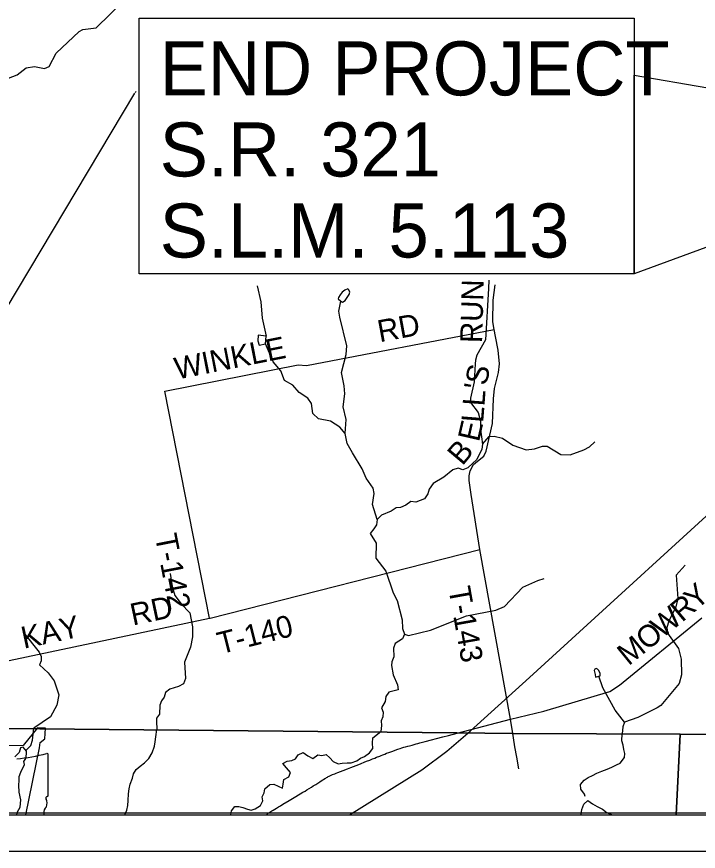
# Model space of a CAD drawing. Extents: x 0 to 34, y 0 to 22.
# Drawn here: x 5.601 to 7.367, y 14 to 16.162 of the extents above; entities that cross this region are included whole.
import ezdxf

# ---------------------------------------------------------------- set-up
doc = ezdxf.new("R2010")
doc.units = 0
for name, color, linetype in [('Default', 7, 'Continuous'), ('GM_X_County_Road', 7, 'Continuous'), ('GM_X_County_Road_Text', 7, 'Continuous'), ('GM_X_Major_River', 7, 'Continuous'), ('GM_X_Minor_Lake', 7, 'Continuous'), ('GM_X_Minor_River', 7, 'Continuous'), ('GM_X_Rail_Line', 7, 'Continuous'), ('GM_X_Township_Road', 7, 'Continuous'), ('GM_X_Township_Road_Text', 7, 'Continuous'), ('SH_Cut_Line', 7, 'Continuous'), ('SH_Data', 7, 'Continuous')]:
    doc.layers.add(name, color=color, linetype=linetype)

msp = doc.modelspace()

# ---------------------------------------------------------------- linework, layer by layer
at = {"layer": 'Default'}
msp.add_line((5.9098, 15.9686), (5.9078, 15.9652), dxfattribs=at)
for points in [[(2.3212, 18.6531), (2.2797, 17.8302), (2.2668, 17.0936), (2.2632, 16.8811), (2.258, 16.7775), (2.1837, 15.746), (2.1, 14.637), (2.1, 14.4457), (2.4012, 14.4298), (2.4436, 14.4284), (2.5802, 14.4232), (3.783, 14.3901), (4.0144, 14.3862), (4.819, 14.3535), (4.9366, 14.3421), (5.2368, 14.8438), (5.4205, 15.1508), (5.9071, 15.964)], [(4.8842, 14.0941), (5.6247, 14.0941), (5.6602, 14.2685), (5.6616, 14.2819), (5.6736, 14.2915), (5.6759, 14.3194), (5.6545, 14.3197), (5.6182, 14.274), (5.4889, 14.273)], [(5.6828, 14.1454), (5.6828, 14.1454), (5.6828, 14.1454), (5.6828, 14.2503)], [(5.3532, 14.2417), (5.3532, 14.0941), (5.6721, 14.0941)]]:
    msp.add_lwpolyline(points, dxfattribs=at)
for points in [[(7.2008, 15.4965), (5.9187, 15.4965), (5.9187, 16.1585), (7.2008, 16.1585)], [(7.2008, 16.011), (8.1557, 15.8464), (7.2008, 15.4965)], [(2.1, 14.4457), (2.1, 14.243), (2.102, 14.2411), (2.1319, 14.2168), (2.1359, 14.2103), (2.1425, 14.1753), (2.1455, 14.1482), (2.1436, 14.1288), (2.1399, 14.114), (2.1382, 14.1043), (2.1342, 14.0941), (7.3096, 14.0941), (7.3204, 14.3032), (6.8864, 14.3056), (6.7418, 14.3069), (5.4793, 14.3187), (5.0616, 14.3309), (4.9366, 14.3421), (4.819, 14.3535), (4.0144, 14.3862), (3.783, 14.3901), (2.5802, 14.4232), (2.4436, 14.4284), (2.4012, 14.4298)], [(7.3096, 14.0941), (8.9, 14.0941), (8.9, 14.2922), (8.7041, 14.2905), (8.6074, 14.2911), (7.3204, 14.3032)]]:
    msp.add_lwpolyline(points, close=True, dxfattribs=at)
for centre, major_axis, start_param, end_param in [((5.5654, 14.518), (0.3495, 0), 4.814394, 5.042369), ((5.6792, 14.2505), (0.00367, 0), 6.197627, 7.989034), ((5.682, 14.1377), (0.00568, 0), 1.883976, 3.671073), ((5.6789, 14.145), (0.00393, 0), 5.054544, 6.418171), ((5.6458, 14.1245), (0.0341, 0), 5.934695, 6.695948), ((5.696, 14.1016), (0.0248, 0), 2.387724, 3.262537), ((5.585, 14.0883), (0.0874, 0), 0.083727, 0.156833)]:
    msp.add_ellipse(centre, major_axis=major_axis, ratio=0.8, start_param=start_param, end_param=end_param, dxfattribs=at)
at = {"layer": 'GM_X_County_Road'}
for points in [[(6.7421, 14.3064), (6.8805, 14.3426), (6.9665, 14.3634), (7.1378, 14.4138), (7.1628, 14.4308), (7.3766, 14.605)], [(6.2486, 14.0941), (6.2487, 14.0942), (6.2501, 14.0959), (6.2513, 14.0971), (6.2528, 14.0984), (6.2544, 14.0996), (6.2569, 14.1014), (6.2598, 14.1033), (6.2625, 14.105), (6.2658, 14.107), (6.2696, 14.1092), (6.2738, 14.1116), (6.2792, 14.1148), (6.2848, 14.1182), (6.2909, 14.1219), (6.3066, 14.1313), (6.3242, 14.1418), (6.3426, 14.1528), (6.3481, 14.1561), (6.3531, 14.1591), (6.359, 14.1627), (6.3645, 14.1662), (6.3694, 14.1694), (6.3758, 14.1735), (6.3861, 14.1801), (6.3922, 14.1839), (6.3963, 14.1864), (6.3994, 14.1883), (6.402, 14.1899), (6.404, 14.1912), (6.4061, 14.1924), (6.4082, 14.1935), (6.4105, 14.1946), (6.414, 14.1962), (6.4196, 14.1986), (6.425, 14.2008), (6.4291, 14.2024), (6.4331, 14.204), (6.4398, 14.2065), (6.4472, 14.2093), (6.4578, 14.2135), (6.4668, 14.217), (6.4876, 14.2253), (6.5078, 14.2333), (6.5158, 14.2364), (6.5233, 14.2393), (6.5289, 14.2416), (6.5336, 14.2435), (6.5417, 14.2468), (6.5456, 14.2484), (6.5495, 14.25), (6.5546, 14.252), (6.5596, 14.2539), (6.5652, 14.256), (6.5708, 14.2581), (6.5755, 14.2598), (6.5817, 14.262), (6.5883, 14.2643), (6.5943, 14.2662), (6.5989, 14.2677), (6.6042, 14.2694), (6.6087, 14.2707), (6.6141, 14.2722), (6.6191, 14.2736), (6.6255, 14.2754), (6.6311, 14.2768), (6.6359, 14.2781), (6.6405, 14.2794), (6.646, 14.2809), (6.6595, 14.2845), (6.7052, 14.2965), (6.7197, 14.3003), (6.7421, 14.3064)]]:
    msp.add_lwpolyline(points, dxfattribs=at)
at = {"layer": 'GM_X_Major_River'}
msp.add_lwpolyline([(7.0636, 14.0941), (7.064, 14.0967), (7.0657, 14.1085), (7.0708, 14.1217), (7.0805, 14.1314), (7.0929, 14.1229), (7.1053, 14.1159), (7.1188, 14.1088), (7.1308, 14.0999), (7.1448, 14.0944), (7.1452, 14.0941)], dxfattribs=at)
at = {"layer": 'GM_X_Minor_Lake'}
for points in [[(6.4411, 15.4251), (6.4448, 15.4227), (6.4525, 15.4272), (6.4575, 15.4351), (6.4625, 15.4422), (6.4645, 15.449), (6.4616, 15.4548), (6.459, 15.4571), (6.4513, 15.4538), (6.4444, 15.4486), (6.4394, 15.4418), (6.4348, 15.435)], [(6.4348, 15.435), (6.4337, 15.4316), (6.4411, 15.4251)], [(6.2461, 15.3145), (6.2475, 15.3342), (6.2266, 15.3368), (6.2257, 15.3228), (6.2289, 15.3117)], [(6.2289, 15.3117), (6.2461, 15.3145)], [(7.1092, 14.4538), (7.1126, 14.4549), (7.1127, 14.4606), (7.1098, 14.4682), (7.1056, 14.4717), (7.1022, 14.4737), (7.0988, 14.4718), (7.0972, 14.468), (7.0994, 14.4619), (7.1001, 14.4577), (7.1012, 14.4513)], [(7.1012, 14.4513), (7.1092, 14.4538)], [(5.601, 14.0941), (5.6033, 14.102), (5.6099, 14.1144), (5.612, 14.1333), (5.607, 14.1531), (5.6065, 14.1717), (5.6078, 14.1835), (5.6075, 14.1937), (5.6118, 14.2047), (5.6212, 14.2246), (5.6198, 14.2323), (5.6244, 14.2405), (5.6268, 14.2526), (5.6262, 14.2591), (5.6176, 14.2702), (5.6108, 14.2677), (5.6072, 14.256), (5.5961, 14.2451)]]:
    msp.add_lwpolyline(points, dxfattribs=at)
at = {"layer": 'GM_X_Minor_River'}
for points in [[(5.5682, 15.9991), (5.6021, 16.0114), (5.6255, 16.03), (5.6472, 16.0335), (5.6729, 16.0282), (5.6851, 16.0329), (5.7034, 16.0675), (5.7625, 16.1235), (5.7721, 16.1287), (5.8067, 16.1331), (5.8805, 16.2048)], [(6.224, 15.4647), (6.2332, 15.4236), (6.2375, 15.3814), (6.2475, 15.3342)], [(6.8242, 15.4795), (6.8232, 15.4579), (6.8156, 15.3251), (6.7934, 15.2852), (6.7898, 15.272), (6.7893, 15.2625), (6.786, 15.2167), (6.7767, 15.1739), (6.7773, 15.1629), (6.797, 15.1368), (6.8028, 15.1143), (6.8028, 15.0931), (6.8084, 15.055), (6.8063, 15.0418), (6.793, 15.0154), (6.7696, 14.9934), (6.7566, 14.9879), (6.7449, 14.993), (6.7308, 14.9886), (6.7074, 14.9692), (6.6802, 14.9529), (6.6701, 14.9386), (6.6666, 14.9262), (6.6573, 14.9134), (6.6351, 14.9046), (6.6219, 14.9059), (6.6092, 14.897), (6.5959, 14.8908), (6.5841, 14.8898), (6.5711, 14.8809), (6.5466, 14.8706), (6.5347, 14.8594), (6.533, 14.8457), (6.5264, 14.8356), (6.5168, 14.8232), (6.5323, 14.7979), (6.5314, 14.7596), (6.5571, 14.7255), (6.5768, 14.6698), (6.5872, 14.6499), (6.5997, 14.5996), (6.6005, 14.5772), (6.6057, 14.5627), (6.6009, 14.5506), (6.5814, 14.5384), (6.5771, 14.5263), (6.5779, 14.5039), (6.5732, 14.4911), (6.5723, 14.4816), (6.5761, 14.4573), (6.5875, 14.4313), (6.5896, 14.4187), (6.5652, 14.4126), (6.5571, 14.401), (6.5554, 14.3877), (6.5464, 14.3719), (6.5504, 14.3601), (6.5499, 14.348), (6.5456, 14.3382), (6.5462, 14.3256), (6.5449, 14.3101)], [(6.5347, 14.8594), (6.5231, 14.8983), (6.5277, 14.927), (6.5245, 14.9407), (6.5063, 14.9664), (6.4964, 14.9913), (6.4715, 15.0326), (6.4571, 15.0563), (6.4521, 15.0822), (6.4546, 15.1186), (6.4467, 15.1514), (6.4517, 15.1855), (6.4493, 15.206), (6.443, 15.2406), (6.4543, 15.2871), (6.4565, 15.3095), (6.4382, 15.3841), (6.4361, 15.399), (6.4411, 15.4251)], [(6.4521, 15.0822), (6.438, 15.0988), (6.4143, 15.1143), (6.3833, 15.1204), (6.3687, 15.1339), (6.3645, 15.1602), (6.3556, 15.1736), (6.333, 15.1883), (6.3166, 15.2076), (6.2948, 15.22), (6.2857, 15.2452), (6.2655, 15.2679), (6.2461, 15.3145)], [(6.8084, 15.055), (6.8254, 15.0749), (6.8379, 15.0751), (6.8594, 15.0702), (6.8865, 15.052), (6.9212, 15.0405), (6.9425, 15.0425), (6.9631, 15.0494), (6.9753, 15.0492), (7.011, 15.0279), (7.0349, 15.0275), (7.0707, 15.0399), (7.0849, 15.0481), (7.0987, 15.0608)], [(7.3333, 14.7409), (7.3098, 14.7151), (7.3143, 14.6547), (7.309, 14.6335), (7.2907, 14.5962), (7.2855, 14.5796), (7.2872, 14.5655), (7.3155, 14.5257), (7.3227, 14.4982), (7.324, 14.4569), (7.318, 14.4349), (7.2705, 14.3779), (7.2602, 14.372), (7.2109, 14.3469), (7.1762, 14.3349), (7.1715, 14.3224), (7.1699, 14.3042)], [(5.9983, 14.7197), (6.0036, 14.6863), (6.0108, 14.663), (6.0272, 14.6411), (6.05, 14.6176), (6.0567, 14.5818), (6.0563, 14.5557), (6.051, 14.5292), (6.036, 14.4896), (6.0381, 14.4474), (6.033, 14.4342), (6.02, 14.4268), (5.9979, 14.4203), (5.9864, 14.4114), (5.9828, 14.3993), (5.9766, 14.3895), (5.9719, 14.3782), (5.9708, 14.3554), (5.9635, 14.3453), (5.9635, 14.337), (5.9644, 14.3159)], [(6.6057, 14.5627), (6.6162, 14.5595), (6.673, 14.5731), (6.7668, 14.6101), (6.8422, 14.625), (6.865, 14.6338), (6.9121, 14.6847), (6.9518, 14.7012), (6.9674, 14.7067)], [(5.6187, 14.5671), (5.6592, 14.5163), (5.6648, 14.5045), (5.6646, 14.4931), (5.6603, 14.4829), (5.6827, 14.4621), (5.698, 14.4417), (5.7103, 14.4051), (5.7047, 14.379), (5.6887, 14.3485), (5.6451, 14.3193)], [(7.1762, 14.3349), (7.1516, 14.3656), (7.1194, 14.4237), (7.1092, 14.4538)], [(5.6248, 14.2609), (5.6373, 14.2741), (5.6417, 14.2877), (5.6451, 14.3193)], [(5.8813, 14.0941), (5.8864, 14.1068), (5.8892, 14.1185), (5.8897, 14.1314), (5.8911, 14.1485), (5.8928, 14.1621), (5.8952, 14.1739), (5.9007, 14.1897), (5.9039, 14.2007), (5.9108, 14.212), (5.9208, 14.2209), (5.9322, 14.2295), (5.9434, 14.2403), (5.9519, 14.255), (5.9585, 14.272), (5.9602, 14.2837), (5.9619, 14.297), (5.9644, 14.3159)], [(6.1562, 14.0941), (6.1562, 14.0946), (6.1574, 14.1048), (6.1663, 14.1157), (6.1765, 14.116), (6.1867, 14.1135), (6.1987, 14.1096), (6.2089, 14.1068), (6.2191, 14.1104), (6.2325, 14.1186), (6.2387, 14.131), (6.2369, 14.1409), (6.242, 14.1511), (6.2436, 14.1617), (6.257, 14.1729), (6.2669, 14.1739), (6.2785, 14.1688), (6.2894, 14.1637), (6.2915, 14.1736), (6.2928, 14.1864), (6.3061, 14.1931), (6.3104, 14.2044), (6.3004, 14.2163), (6.291, 14.2274), (6.3021, 14.2334), (6.3138, 14.2351), (6.3234, 14.2399), (6.3307, 14.25), (6.3432, 14.2559), (6.3556, 14.2474), (6.368, 14.2408), (6.381, 14.2497), (6.3916, 14.2481), (6.4026, 14.251), (6.4127, 14.2425), (6.4208, 14.2325), (6.4336, 14.2263), (6.4446, 14.228), (6.4575, 14.2293), (6.4681, 14.2296), (6.4825, 14.2343), (6.4921, 14.241), (6.5023, 14.2454), (6.5153, 14.2551), (6.5242, 14.2664), (6.5232, 14.2804), (6.5238, 14.2941), (6.5449, 14.3101)], [(7.0742, 14.1421), (7.072, 14.1483), (7.0631, 14.1613), (7.0621, 14.1731), (7.0717, 14.1847), (7.0816, 14.1911), (7.0927, 14.1966), (7.1041, 14.2021), (7.117, 14.2073), (7.1311, 14.2132), (7.1429, 14.2183), (7.1551, 14.2242), (7.1646, 14.2287), (7.1758, 14.2426), (7.1767, 14.2532), (7.1745, 14.2634), (7.1724, 14.2752), (7.1692, 14.2859), (7.1699, 14.3042)]]:
    msp.add_lwpolyline(points, dxfattribs=at)
at = {"layer": 'GM_X_Rail_Line'}
for points in [[(6.7762, 14.3109), (6.9297, 14.4507), (7.5373, 15.0047), (7.83, 15.2691), (7.9287, 15.3625), (7.9592, 15.3949), (8.0363, 15.4875), (8.1684, 15.6475), (8.1886, 15.6755), (8.2095, 15.7107), (8.2296, 15.7554), (8.4079, 16.5494), (8.4762, 16.897), (8.4969, 16.9945), (8.5214, 17.0999), (8.5608, 17.4879), (8.571, 17.5663), (8.6067, 17.7431), (8.6649, 18.0046), (8.6886, 18.0902), (8.7141, 18.1631), (8.8658, 18.463), (8.9, 18.5325)], [(6.4632, 14.0941), (6.6505, 14.2108), (6.7154, 14.2595), (6.7762, 14.3109)]]:
    msp.add_lwpolyline(points, dxfattribs=at)
at = {"layer": 'GM_X_Township_Road'}
msp.add_line((6.1021, 14.6044), (6.8008, 14.7816), dxfattribs=at)
for points in [[(6.8867, 14.3051), (6.8805, 14.3426), (6.8008, 14.7816), (6.7782, 14.924), (6.7735, 14.9605), (6.7734, 14.973), (6.7759, 14.9859), (6.7849, 15.0021), (6.7992, 15.014), (6.8111, 15.0233), (6.8174, 15.0368), (6.8335, 15.1079), (6.8365, 15.1724), (6.8389, 15.199), (6.8491, 15.2402), (6.8521, 15.2633), (6.8486, 15.2987), (6.8416, 15.3341), (6.8383, 15.352), (6.8347, 15.3719), (6.8353, 15.4281), (6.8405, 15.4675)], [(6.1002, 14.6039), (5.9849, 15.1925), (6.3303, 15.2606), (6.3523, 15.259), (6.8383, 15.352)], [(5.0618, 14.3304), (5.1587, 14.4108), (5.4443, 14.4648), (5.5651, 14.4908), (6.1002, 14.6039), (6.1021, 14.6044)], [(6.902, 14.2138), (6.8967, 14.2435), (6.8921, 14.2708), (6.8883, 14.2939), (6.8867, 14.3051)]]:
    msp.add_lwpolyline(points, dxfattribs=at)
at = {"layer": 'SH_Cut_Line'}
msp.add_lwpolyline([(2.3212, 18.6531), (2.2797, 17.8302), (2.2668, 17.0936), (2.2632, 16.8811), (2.258, 16.7775), (2.1837, 15.746), (2.1, 14.637), (2.1, 14.4457), (2.4012, 14.4298), (2.4436, 14.4284), (2.5802, 14.4232), (3.783, 14.3901), (4.0144, 14.3862), (4.819, 14.3535), (4.9366, 14.3421), (5.0616, 14.3309), (5.4793, 14.3187), (6.7418, 14.3069), (6.8864, 14.3056), (7.3204, 14.3032), (8.6074, 14.2911), (8.7041, 14.2905), (8.9, 14.2922), (8.9, 20.8941)], dxfattribs=at)
at = {"layer": 'SH_Data'}
for p, q in [((2.1, 14.1), (8.9, 14.1)), ((2, 14), (9, 14))]:
    msp.add_line(p, q, dxfattribs=at)

# ---------------------------------------------------------------- texts
at = {"layer": 'Default'}
for s, p in [('END PROJECT', (5.9716, 15.9583)), ('S.R. 321', (5.9716, 15.7483)), ('S.L.M. 5.113', (5.9716, 15.5383))]:
    msp.add_text(s, height=0.14, dxfattribs=at).set_placement(p)
at = {"layer": 'GM_X_County_Road_Text'}
for s, rotation, p in [('Y', 42.1619, (7.3622, 14.6234)), ('R', 40.1081, (7.3248, 14.5919)), ('W', 39.1979, (7.273, 14.5497)), ('O', 39.1855, (7.2343, 14.5181)), ('M', 39.1861, (7.1865, 14.4791))]:
    msp.add_text(s, height=0.0568, rotation=rotation, dxfattribs=at).set_placement(p)
at = {"layer": 'GM_X_Township_Road_Text'}
for s, height, rotation, p in [('RUN', 0.05682, 88.3727, (6.8068, 15.3161)), ('RD', 0.05682, 10.4374, (6.5416, 15.3187)), ('WINKLE', 0.05682, 11.2413, (6.0162, 15.222)), ('S', 0.0568, 76.8546, (6.8175, 15.2043)), ("'", 0.0568, 81.6587, (6.8159, 15.1932)), ('L', 0.0568, 85.9129, (6.813, 15.1519)), ('L', 0.0568, 85.4847, (6.8096, 15.1091)), ('E', 0.0568, 77.103, (6.7987, 15.0587)), ('B', 0.0568, 49.9311, (6.7557, 14.9969)), ('T-142', 0.05682, 281.0346, (5.9588, 14.8171)), ('T-143', 0.05682, 280.1546, (6.7194, 14.681)), ('RD', 0.05682, 11.9901, (5.9019, 14.5846)), ('KAY', 0.05682, 12.1175, (5.6194, 14.5246)), ('T-140', 0.05682, 14.1721, (6.1289, 14.5103))]:
    msp.add_text(s, height=height, rotation=rotation, dxfattribs=at).set_placement(p)

doc.saveas('drawing.dxf')
